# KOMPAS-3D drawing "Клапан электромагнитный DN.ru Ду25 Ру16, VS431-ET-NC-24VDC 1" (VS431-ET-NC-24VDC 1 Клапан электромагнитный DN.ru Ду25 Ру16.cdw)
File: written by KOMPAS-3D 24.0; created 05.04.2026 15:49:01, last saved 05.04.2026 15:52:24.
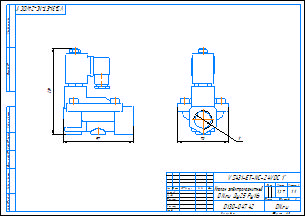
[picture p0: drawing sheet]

Document properties: c3d_UniqueCompID: ef56311e-7521-43dc-8291-0e6108b3d81d; Автор: artio; Класс точности: c; Знак неуказанной шероховатости: Шероховатость не задана; Рассекать на разрезах: Да; c3d_UniqueCompID: ef56311e-7521-43dc-8291-0e6108b3d81d; Автор: artio; Класс точности: c; Знак неуказанной шероховатости: Шероховатость не задана; Рассекать на разрезах: Да; Автор: artio; Форматы листов документа: A3; Полное имя файла: VS431-ET-NC-24VDC 1 Клапан электромагнитный DN.ru Ду25 Ру16.m3d; Масса: 1.267; Наименование: Клапан электромагнитный DN.ru Ду25 Ру16; Количество листов документа: 1; Примечание: D130-04742

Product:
- Body: Тело 1  | qty 1
    Масса: 1.729172
- Part/product: Клапан электромагнитный DN.ru Ду25 Ру16  | designation VS431-ET-NC-24VDC 1
    Масса: 1.267
    Раздел спецификации: Прочие изделия
    Примечание: D130-04742
    additional columns: ef56311e-7521-43dc-8291-0e6108b3d81d; artio; c; Шероховатость не задана; Да

Views: Вид 1, Спереди, Проекционный вид 2
Referenced files in C:\Users\artio\OneDrive\Рабочий стол\Клапан электромагнитный DN.ru\VS431\VS431-ET-NC\: VS431-ET-NC-24VDC 3-4 Клапан электромагнитный DN.ru Ду20 Ру16.m3d, VS431-ET-NC-24VDC 1 Клапан электромагнитный DN.ru Ду25 Ру16.m3d, VS431-ET-NC-24VDC 3-4 Клапан электромагнитный DN.ru Ду20 Ру16.cdw
Referenced files in C:\Users\artio\OneDrive\Рабочий стол\Клапан электромагнитный DN.ru\VS431\VS431-ET-NC\VS431-ET-NC-24VDC\Ду25\: VS431-ET-NC-24VDC 1 Клапан электромагнитный DN.ru Ду25 Ру16.m3d
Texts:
  VS431-ET-NC-24VDC 1
  Клапан электромагнитный
  DN.ru Ду25 Ру16
  VS431-ET-NC-24VDC 1"
  VS431-ET-NC-24VDC 1"-
  Клапан электромагнитный DN.ru Ду25 Ру16
  VS431-ET-NC-24VDC 1 Клапан электромагнитный DN.ru Ду25 Ру16
Dimensions and other numbers on the sheet: 0; 3; 2; 4; 70; 97; 119; 1:1; 1; 1,27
